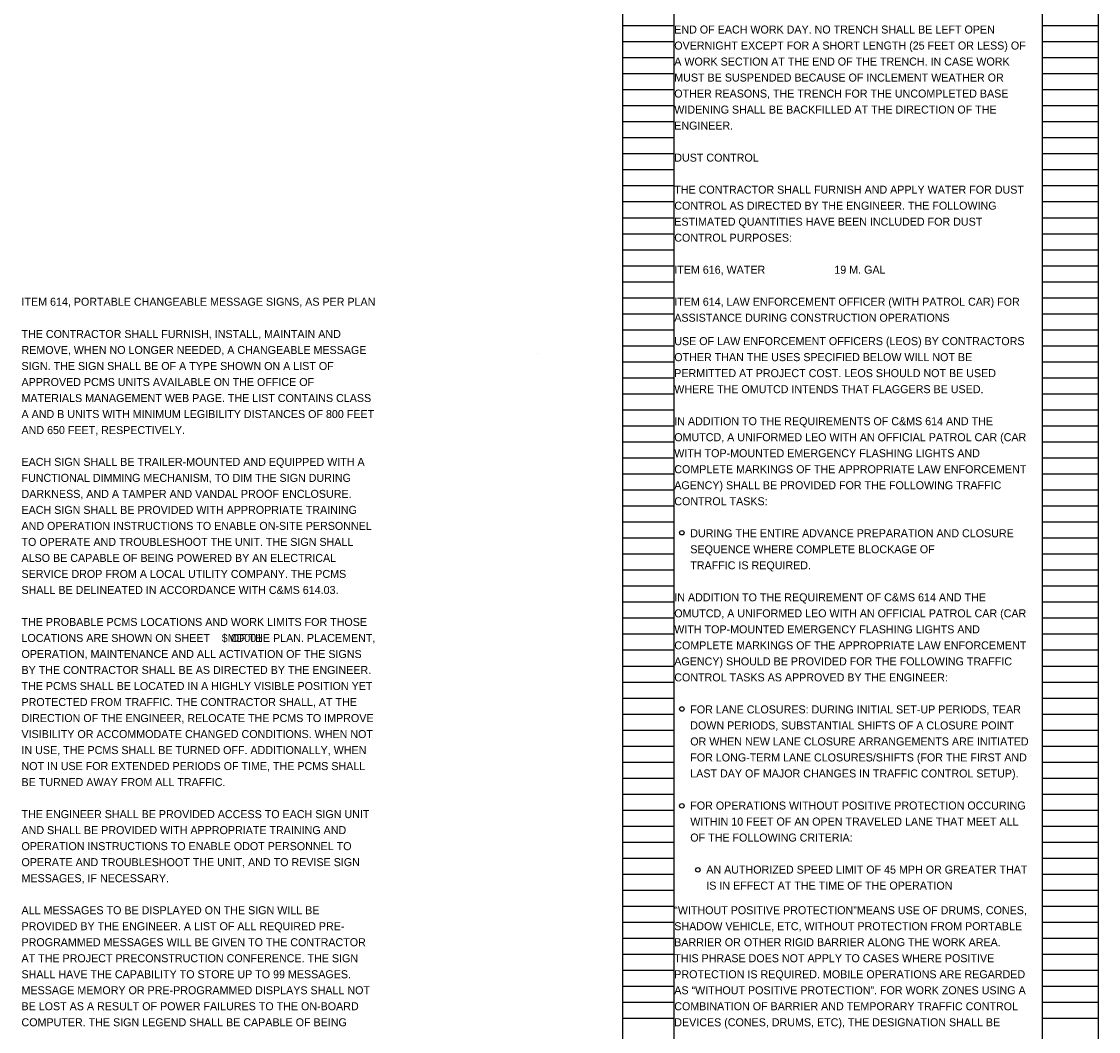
# Model space of a CAD drawing. Extents: x -9 to 32, y -122 to 20.
# Drawn here: x -9.3 to 9.54, y -32.68 to -15.02 of the extents above; entities that cross this region are included whole.
import ezdxf

# ---------------------------------------------------------------- set-up
doc = ezdxf.new("R2010")
doc.units = 0
doc.layers.add('SC_Scratch1', color=7, linetype='Continuous')
doc.layers.add('SH_Text', color=7, linetype='Continuous')

msp = doc.modelspace()

# ---------------------------------------------------------------- linework, layer by layer
at = {"layer": 'SC_Scratch1'}
for p, q in [((1.216, -19.854), (1.216, 0.306)), ((2.116, -19.854), (2.116, 0.306)), ((8.556, -19.854), (8.556, 0.306)), ((9.536, -19.854), (9.536, 0.306)), ((1.216, -15.094), (2.116, -15.094)), ((8.556, -15.094), (9.536, -15.094)), ((1.216, -15.374), (2.116, -15.374)), ((8.556, -15.374), (9.536, -15.374)), ((1.216, -15.654), (2.116, -15.654)), ((8.556, -15.654), (9.536, -15.654)), ((1.216, -15.934), (2.116, -15.934)), ((8.556, -15.934), (9.536, -15.934)), ((1.216, -16.214), (2.116, -16.214)), ((8.556, -16.214), (9.536, -16.214)), ((1.216, -16.494), (2.116, -16.494)), ((8.556, -16.494), (9.536, -16.494)), ((1.216, -16.774), (2.116, -16.774)), ((8.556, -16.774), (9.536, -16.774)), ((1.216, -17.054), (2.116, -17.054)), ((8.556, -17.054), (9.536, -17.054)), ((1.216, -17.334), (2.116, -17.334)), ((8.556, -17.334), (9.536, -17.334)), ((1.216, -17.614), (2.116, -17.614)), ((8.556, -17.614), (9.536, -17.614)), ((1.216, -17.894), (2.116, -17.894)), ((8.556, -17.894), (9.536, -17.894)), ((1.216, -18.174), (2.116, -18.174)), ((8.556, -18.174), (9.536, -18.174)), ((1.216, -18.454), (2.116, -18.454)), ((8.556, -18.454), (9.536, -18.454)), ((1.216, -18.734), (2.116, -18.734)), ((8.556, -18.734), (9.536, -18.734)), ((1.216, -19.014), (2.116, -19.014)), ((8.556, -19.014), (9.536, -19.014)), ((1.216, -19.294), (2.116, -19.294)), ((8.556, -19.294), (9.536, -19.294)), ((1.216, -19.574), (2.116, -19.574)), ((8.556, -19.574), (9.536, -19.574)), ((1.216, -19.854), (2.116, -19.854)), ((1.216, -40.014), (1.216, -19.854)), ((1.216, -19.854), (2.116, -19.854)), ((2.116, -40.014), (2.116, -19.854)), ((8.556, -19.854), (9.536, -19.854)), ((8.556, -40.014), (8.556, -19.854)), ((8.556, -19.854), (9.536, -19.854)), ((9.536, -40.014), (9.536, -19.854)), ((1.216, -20.134), (2.116, -20.134)), ((8.556, -20.134), (9.536, -20.134)), ((1.216, -20.414), (2.116, -20.414)), ((8.556, -20.414), (9.536, -20.414)), ((1.216, -20.694), (2.116, -20.694)), ((8.556, -20.694), (9.536, -20.694)), ((-0.284, -20.834), (-0.284, -20.834)), ((1.216, -20.974), (2.116, -20.974)), ((8.556, -20.974), (9.536, -20.974)), ((1.216, -21.254), (2.116, -21.254)), ((8.556, -21.254), (9.536, -21.254)), ((1.216, -21.534), (2.116, -21.534)), ((8.556, -21.534), (9.536, -21.534)), ((1.216, -21.814), (2.116, -21.814)), ((8.556, -21.814), (9.536, -21.814)), ((1.216, -22.094), (2.116, -22.094)), ((8.556, -22.094), (9.536, -22.094)), ((1.216, -22.374), (2.116, -22.374)), ((8.556, -22.374), (9.536, -22.374)), ((1.216, -22.654), (2.116, -22.654)), ((8.556, -22.654), (9.536, -22.654)), ((1.216, -22.934), (2.116, -22.934)), ((8.556, -22.934), (9.536, -22.934)), ((1.216, -23.214), (2.116, -23.214)), ((8.556, -23.214), (9.536, -23.214)), ((1.216, -23.494), (2.116, -23.494)), ((8.556, -23.494), (9.536, -23.494)), ((1.216, -23.774), (2.116, -23.774)), ((8.556, -23.774), (9.536, -23.774)), ((1.216, -24.054), (2.116, -24.054)), ((8.556, -24.054), (9.536, -24.054)), ((1.216, -24.334), (2.116, -24.334)), ((8.556, -24.334), (9.536, -24.334)), ((1.216, -24.614), (2.116, -24.614)), ((8.556, -24.614), (9.536, -24.614)), ((1.216, -24.894), (2.116, -24.894)), ((8.556, -24.894), (9.536, -24.894)), ((1.216, -25.174), (2.116, -25.174)), ((8.556, -25.174), (9.536, -25.174)), ((1.216, -25.454), (2.116, -25.454)), ((8.556, -25.454), (9.536, -25.454)), ((1.216, -25.734), (2.116, -25.734)), ((8.556, -25.734), (9.536, -25.734)), ((1.216, -26.014), (2.116, -26.014)), ((8.556, -26.014), (9.536, -26.014)), ((1.216, -26.294), (2.116, -26.294)), ((8.556, -26.294), (9.536, -26.294)), ((1.216, -26.574), (2.116, -26.574)), ((8.556, -26.574), (9.536, -26.574)), ((1.216, -26.854), (2.116, -26.854)), ((8.556, -26.854), (9.536, -26.854)), ((1.216, -27.134), (2.116, -27.134)), ((8.556, -27.134), (9.536, -27.134)), ((1.216, -27.414), (2.116, -27.414)), ((8.556, -27.414), (9.536, -27.414)), ((1.216, -27.694), (2.116, -27.694)), ((8.556, -27.694), (9.536, -27.694)), ((1.216, -27.974), (2.116, -27.974)), ((8.556, -27.974), (9.536, -27.974)), ((1.216, -28.254), (2.116, -28.254)), ((8.556, -28.254), (9.536, -28.254)), ((1.216, -28.534), (2.116, -28.534)), ((8.556, -28.534), (9.536, -28.534)), ((1.216, -28.814), (2.116, -28.814)), ((8.556, -28.814), (9.536, -28.814)), ((1.216, -29.094), (2.116, -29.094)), ((8.556, -29.094), (9.536, -29.094)), ((1.216, -29.374), (2.116, -29.374)), ((8.556, -29.374), (9.536, -29.374)), ((1.216, -29.654), (2.116, -29.654)), ((8.556, -29.654), (9.536, -29.654)), ((1.216, -29.934), (2.116, -29.934)), ((8.556, -29.934), (9.536, -29.934)), ((1.216, -30.214), (2.116, -30.214)), ((8.556, -30.214), (9.536, -30.214)), ((1.216, -30.494), (2.116, -30.494)), ((8.556, -30.494), (9.536, -30.494)), ((1.216, -30.774), (2.116, -30.774)), ((8.556, -30.774), (9.536, -30.774)), ((1.216, -31.054), (2.116, -31.054)), ((8.556, -31.054), (9.536, -31.054)), ((1.216, -31.334), (2.116, -31.334)), ((8.556, -31.334), (9.536, -31.334)), ((1.216, -31.614), (2.116, -31.614)), ((8.556, -31.614), (9.536, -31.614)), ((1.216, -31.894), (2.116, -31.894)), ((8.556, -31.894), (9.536, -31.894)), ((1.216, -32.174), (2.116, -32.174)), ((8.556, -32.174), (9.536, -32.174)), ((1.216, -32.454), (2.116, -32.454)), ((8.556, -32.454), (9.536, -32.454))]:
    msp.add_line(p, q, dxfattribs=at)
at = {"layer": 'SH_Text'}
for centre in [(2.249, -23.964), (2.249, -27.045), (2.249, -28.739), (2.529, -29.859)]:
    msp.add_circle(centre, 0.0389, dxfattribs=at)

# ---------------------------------------------------------------- texts
for s, p in [('END OF EACH WORK DAY. NO TRENCH SHALL BE LEFT OPEN ', (2.116, -15.234)), ('OVERNIGHT EXCEPT FOR A SHORT LENGTH (25 FEET OR LESS) OF ', (2.116, -15.514)), ('A WORK SECTION AT THE END OF THE TRENCH. IN CASE WORK ', (2.116, -15.794)), ('MUST BE SUSPENDED BECAUSE OF INCLEMENT WEATHER OR ', (2.116, -16.074)), ('OTHER REASONS, THE TRENCH FOR THE UNCOMPLETED BASE ', (2.116, -16.354)), ('WIDENING SHALL BE BACKFILLED AT THE DIRECTION OF THE ', (2.116, -16.634)), ('ENGINEER.', (2.116, -16.914)), ('DUST CONTROL', (2.116, -17.474)), ('THE CONTRACTOR SHALL FURNISH AND APPLY WATER FOR DUST ', (2.116, -18.034)), ('CONTROL AS DIRECTED BY THE ENGINEER. THE FOLLOWING ', (2.116, -18.314)), ('ESTIMATED QUANTITIES HAVE BEEN INCLUDED FOR DUST ', (2.116, -18.594)), ('CONTROL PURPOSES:', (2.116, -18.874)), ('ITEM 616, WATER', (2.116, -19.434)), ('19 M. GAL', (4.916, -19.434)), ('ITEM 614, PORTABLE CHANGEABLE MESSAGE SIGNS, AS PER PLAN', (-9.302, -19.994)), ('ITEM 614, LAW ENFORCEMENT OFFICER (WITH PATROL CAR) FOR ', (2.116, -19.994)), ('ASSISTANCE DURING CONSTRUCTION OPERATIONS', (2.116, -20.274)), ('THE CONTRACTOR SHALL FURNISH, INSTALL, MAINTAIN AND ', (-9.302, -20.558)), ('REMOVE, WHEN NO LONGER NEEDED, A CHANGEABLE MESSAGE ', (-9.302, -20.838)), ('USE OF LAW ENFORCEMENT OFFICERS (LEOS) BY CONTRACTORS ', (2.116, -20.683)), ('OTHER THAN THE USES SPECIFIED BELOW WILL NOT BE ', (2.116, -20.963)), ('SIGN. THE SIGN SHALL BE OF A TYPE SHOWN ON A LIST OF ', (-9.302, -21.118)), ('APPROVED PCMS UNITS AVAILABLE ON THE OFFICE OF ', (-9.302, -21.398)), ('PERMITTED AT PROJECT COST. LEOS SHOULD NOT BE USED ', (2.116, -21.243)), ('WHERE THE OMUTCD INTENDS THAT FLAGGERS BE USED.', (2.116, -21.523)), ('MATERIALS MANAGEMENT WEB PAGE. THE LIST CONTAINS CLASS ', (-9.302, -21.678)), ('A AND B UNITS WITH MINIMUM LEGIBILITY DISTANCES OF 800 FEET ', (-9.302, -21.958)), ('IN ADDITION TO THE REQUIREMENTS OF C&MS 614 AND THE ', (2.116, -22.083)), ('AND 650 FEET, RESPECTIVELY.', (-9.302, -22.238)), ('OMUTCD, A UNIFORMED LEO WITH AN OFFICIAL PATROL CAR (CAR ', (2.116, -22.363)), ('WITH TOP-MOUNTED EMERGENCY FLASHING LIGHTS AND ', (2.116, -22.643)), ('EACH SIGN SHALL BE TRAILER-MOUNTED AND EQUIPPED WITH A ', (-9.302, -22.794)), ('COMPLETE MARKINGS OF THE APPROPRIATE LAW ENFORCEMENT ', (2.116, -22.923)), ('FUNCTIONAL DIMMING MECHANISM, TO DIM THE SIGN DURING ', (-9.302, -23.074)), ('AGENCY) SHALL BE PROVIDED FOR THE FOLLOWING TRAFFIC ', (2.116, -23.203)), ('DARKNESS, AND A TAMPER AND VANDAL PROOF ENCLOSURE. ', (-9.302, -23.354)), ('CONTROL TASKS:', (2.116, -23.483)), ('EACH SIGN SHALL BE PROVIDED WITH APPROPRIATE TRAINING ', (-9.302, -23.634)), ('AND OPERATION INSTRUCTIONS TO ENABLE ON-SITE PERSONNEL ', (-9.302, -23.914)), ('DURING THE ENTIRE ADVANCE PREPARATION AND CLOSURE ', (2.396, -24.043)), ('TO OPERATE AND TROUBLESHOOT THE UNIT. THE SIGN SHALL ', (-9.302, -24.194)), ('SEQUENCE WHERE COMPLETE BLOCKAGE OF', (2.396, -24.323)), ('ALSO BE CAPABLE OF BEING POWERED BY AN ELECTRICAL ', (-9.302, -24.474)), ('TRAFFIC IS REQUIRED.', (2.396, -24.603)), ('SERVICE DROP FROM A LOCAL UTILITY COMPANY. THE PCMS ', (-9.302, -24.754)), ('SHALL BE DELINEATED IN ACCORDANCE WITH C&MS 614.03.', (-9.302, -25.034)), ('IN ADDITION TO THE REQUIREMENT OF C&MS 614 AND THE ', (2.116, -25.163)), ('OMUTCD, A UNIFORMED LEO WITH AN OFFICIAL PATROL CAR (CAR ', (2.116, -25.443)), ('THE PROBABLE PCMS LOCATIONS AND WORK LIMITS FOR THOSE ', (-9.302, -25.594)), ('WITH TOP-MOUNTED EMERGENCY FLASHING LIGHTS AND ', (2.116, -25.723)), ('LOCATIONS ARE SHOWN ON SHEET       OF THE PLAN. PLACEMENT, ', (-9.302, -25.874)), ('$MD001', (-5.8, -25.874)), ('COMPLETE MARKINGS OF THE APPROPRIATE LAW ENFORCEMENT ', (2.116, -26.003)), ('OPERATION, MAINTENANCE AND ALL ACTIVATION OF THE SIGNS ', (-9.302, -26.154)), ('AGENCY) SHOULD BE PROVIDED FOR THE FOLLOWING TRAFFIC ', (2.116, -26.283)), ('BY THE CONTRACTOR SHALL BE AS DIRECTED BY THE ENGINEER. ', (-9.302, -26.434)), ('CONTROL TASKS AS APPROVED BY THE ENGINEER:', (2.116, -26.563)), ('THE PCMS SHALL BE LOCATED IN A HIGHLY VISIBLE POSITION YET ', (-9.302, -26.714)), ('PROTECTED FROM TRAFFIC. THE CONTRACTOR SHALL, AT THE ', (-9.302, -26.994)), ('FOR LANE CLOSURES: DURING INITIAL SET-UP PERIODS, TEAR ', (2.396, -27.123)), ('DIRECTION OF THE ENGINEER, RELOCATE THE PCMS TO IMPROVE ', (-9.302, -27.274)), ('DOWN PERIODS, SUBSTANTIAL SHIFTS OF A CLOSURE POINT ', (2.396, -27.403)), ('VISIBILITY OR ACCOMMODATE CHANGED CONDITIONS. WHEN NOT ', (-9.302, -27.554)), ('OR WHEN NEW LANE CLOSURE ARRANGEMENTS ARE INITIATED ', (2.396, -27.683)), ('IN USE, THE PCMS SHALL BE TURNED OFF. ADDITIONALLY, WHEN ', (-9.302, -27.834)), ('FOR LONG-TERM LANE CLOSURES/SHIFTS (FOR THE FIRST AND ', (2.396, -27.963)), ('NOT IN USE FOR EXTENDED PERIODS OF TIME, THE PCMS SHALL ', (-9.302, -28.114)), ('BE TURNED AWAY FROM ALL TRAFFIC.', (-9.302, -28.394)), ('LAST DAY OF MAJOR CHANGES IN TRAFFIC CONTROL SETUP).', (2.396, -28.243)), ('THE ENGINEER SHALL BE PROVIDED ACCESS TO EACH SIGN UNIT ', (-9.302, -28.954)), ('FOR OPERATIONS WITHOUT POSITIVE PROTECTION OCCURING ', (2.396, -28.804)), ('WITHIN 10 FEET OF AN OPEN TRAVELED LANE THAT MEET ALL ', (2.396, -29.084)), ('AND SHALL BE PROVIDED WITH APPROPRIATE TRAINING AND ', (-9.302, -29.234)), ('OPERATION INSTRUCTIONS TO ENABLE ODOT PERSONNEL TO ', (-9.302, -29.514)), ('OF THE FOLLOWING CRITERIA:', (2.396, -29.364)), ('OPERATE AND TROUBLESHOOT THE UNIT, AND TO REVISE SIGN ', (-9.302, -29.794)), ('MESSAGES, IF NECESSARY.', (-9.302, -30.074)), ('AN AUTHORIZED SPEED LIMIT OF 45 MPH OR GREATER THAT ', (2.676, -29.924)), ('IS IN EFFECT AT THE TIME OF THE OPERATION', (2.676, -30.204)), ('ALL MESSAGES TO BE DISPLAYED ON THE SIGN WILL BE ', (-9.302, -30.634)), ('“WITHOUT POSITIVE PROTECTION”MEANS USE OF DRUMS, CONES, ', (2.116, -30.634)), ('PROVIDED BY THE ENGINEER. A LIST OF ALL REQUIRED PRE-', (-9.302, -30.914)), ('SHADOW VEHICLE, ETC, WITHOUT PROTECTION FROM PORTABLE ', (2.116, -30.914)), ('PROGRAMMED MESSAGES WILL BE GIVEN TO THE CONTRACTOR ', (-9.302, -31.194)), ('BARRIER OR OTHER RIGID BARRIER ALONG THE WORK AREA. ', (2.116, -31.194)), ('AT THE PROJECT PRECONSTRUCTION CONFERENCE. THE SIGN ', (-9.302, -31.474)), ('THIS PHRASE DOES NOT APPLY TO CASES WHERE POSITIVE ', (2.116, -31.474)), ('SHALL HAVE THE CAPABILITY TO STORE UP TO 99 MESSAGES. ', (-9.302, -31.754)), ('PROTECTION IS REQUIRED. MOBILE OPERATIONS ARE REGARDED ', (2.116, -31.754)), ('MESSAGE MEMORY OR PRE-PROGRAMMED DISPLAYS SHALL NOT ', (-9.302, -32.034)), ('AS “WITHOUT POSITIVE PROTECTION”. FOR WORK ZONES USING A ', (2.116, -32.034)), ('BE LOST AS A RESULT OF POWER FAILURES TO THE ON-BOARD ', (-9.302, -32.314)), ('COMBINATION OF BARRIER AND TEMPORARY TRAFFIC CONTROL ', (2.116, -32.314)), ('COMPUTER. THE SIGN LEGEND SHALL BE CAPABLE OF BEING ', (-9.302, -32.594)), ('DEVICES (CONES, DRUMS, ETC), THE DESIGNATION SHALL BE ', (2.116, -32.594))]:
    msp.add_text(s, height=0.14, dxfattribs=at).set_placement(p)

doc.saveas('drawing.dxf')
